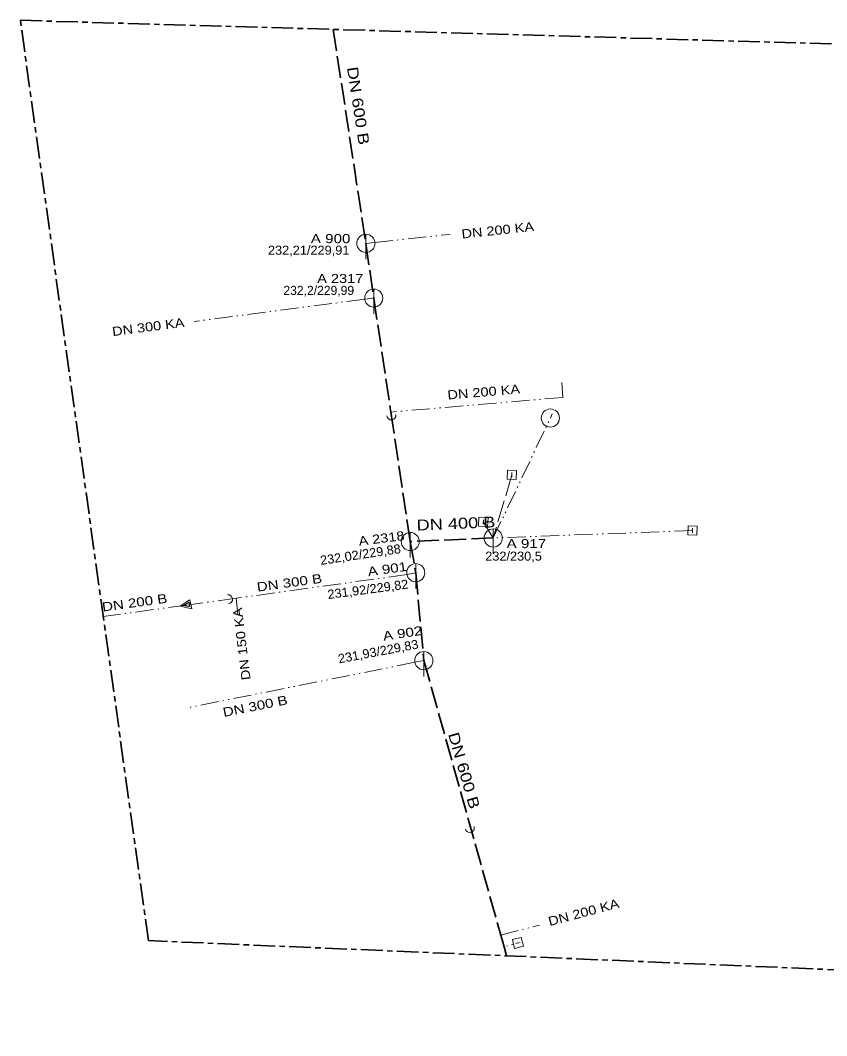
# Model space of a CAD drawing. Extents: x -640241 to -639979, y -1041484 to -1041371.
# Drawn here: x -640241 to -640152.1, y -1041482.8 to -1041370.7 of the extents above; entities that cross this region are included whole.
import ezdxf
from ezdxf.enums import TextEntityAlignment as Align

# ---------------------------------------------------------------- set-up
doc = ezdxf.new("R2010")
doc.units = 0
doc.header["$LTSCALE"] = 0.4
for name, pattern in [('DASH_DOUBLE_DOT', [9.2, 5, -1.2, 0.3, -1.2, 0.3, -1.2]), ('DOTTED', [1.5, 0.3, -1.2]), ('LONG_DASH_SHORT_DASH', [9.9, 6, -1.2, 1.5, -1.2]), ('LONG_DASHED', [7.5, 6, -1.5])]:
    doc.linetypes.add(name, pattern=pattern)
for name, color, linetype, lineweight in [('1', 7, 'LONG_DASH_SHORT_DASH', 35), ('10', 7, 'Continuous', 13), ('14', 7, 'Continuous', 13), ('23', 7, 'LONG_DASHED', 35), ('34', 7, 'DASH_DOUBLE_DOT', 13), ('35', 7, 'LONG_DASHED', 13), ('36', 7, 'DASH_DOUBLE_DOT', 13)]:
    doc.layers.add(name, color=color, linetype=linetype, lineweight=lineweight)
doc.layers.add('29', color=7, linetype='Continuous')
doc.layers.add('39', color=7, linetype='Continuous')

msp = doc.modelspace()

# ---------------------------------------------------------------- linework, layer by layer
at = {"layer": '1'}
msp.add_lwpolyline([(-639990.066, -1041378.027), (-639979.473, -1041482.75), (-640226.879, -1041472.267), (-640241.004, -1041370.744)], close=True, dxfattribs=at)
at = {"layer": '10'}
for p, q in [((-640202.895, -1041394.347), (-640202.895, -1041397.095)), ((-640202.023, -1041400.384), (-640202.023, -1041403.132)), ((-640186.779, -1041420.64), (-640186.801, -1041421.14)), ((-640189.929, -1041425.83), (-640189.951, -1041426.33)), ((-640198, -1041427.24), (-640198, -1041429.988)), ((-640188.85, -1041426.85), (-640188.85, -1041429.598)), ((-640166.859, -1041426.78), (-640166.881, -1041427.28)), ((-640197.39, -1041430.68), (-640197.39, -1041433.428)), ((-640196.5, -1041440.38), (-640196.5, -1041443.128)), ((-640185.879, -1041472.457), (-640186.364, -1041472.579))]:
    msp.add_line(p, q, dxfattribs=at)
for points in [[(-640187.268, -1041420.369), (-640187.311, -1041421.368), (-640186.311, -1041421.41), (-640186.269, -1041420.411)], [(-640190.418, -1041425.559), (-640190.462, -1041426.558), (-640189.463, -1041426.602), (-640189.419, -1041425.603)], [(-640167.348, -1041426.509), (-640167.392, -1041427.508), (-640166.393, -1041427.552), (-640166.349, -1041426.553)], [(-640222.104, -1041435.65), (-640222.293, -1041434.668), (-640223.377, -1041435.385)], [(-640222.293, -1041435.456), (-640222.398, -1041434.915), (-640222.994, -1041435.311)], [(-640185.758, -1041471.912), (-640186.728, -1041472.154), (-640186.485, -1041473.125), (-640185.515, -1041472.882)]]:
    msp.add_lwpolyline(points, close=True, dxfattribs=at)
for centre, radius in [((-640202.8947, -1041395.3473), 1.0002), ((-640202.0227, -1041401.3843), 1.0002), ((-640182.5459, -1041414.6158), 1), ((-640197.9997, -1041428.2403), 1.0002), ((-640188.8497, -1041427.8503), 1.0002), ((-640197.3897, -1041431.6803), 1.0002), ((-640196.4997, -1041441.3803), 1.0002)]:
    msp.add_circle(centre, radius, dxfattribs=at)
at = {"layer": '14'}
for centre, start, end in [((-640200.0859, -1041414.318), 188.5195, 8.5195), ((-640218.0997, -1041434.6169), 277.86851, 97.86851), ((-640191.4295, -1041459.83), 196.04393, 16.04393)]:
    msp.add_arc(centre, 0.5, start, end, dxfattribs=at)
at = {"layer": '23'}
for p, q in [((-640206.498, -1041371.745), (-640202.895, -1041395.347)), ((-640202.895, -1041395.347), (-640202.023, -1041401.384)), ((-640188.85, -1041427.85), (-640198, -1041428.24)), ((-640197.39, -1041431.68), (-640196.5, -1041441.38)), ((-640187.654, -1041472.959), (-640187.371, -1041473.941))]:
    msp.add_line(p, q, dxfattribs=at)
for points in [[(-640202.023, -1041401.384), (-640200.14, -1041413.954), (-640198, -1041428.24), (-640197.39, -1041431.68)], [(-640196.5, -1041441.38), (-640188.022, -1041471.678), (-640187.654, -1041472.959)]]:
    msp.add_lwpolyline(points, dxfattribs=at)
at = {"layer": '34'}
for p, q in [((-640201.901, -1041395.241), (-640193.6, -1041394.357)), ((-640202.895, -1041395.347), (-640201.901, -1041395.241)), ((-640203.015, -1041401.514), (-640221.848, -1041403.974)), ((-640202.023, -1041401.384), (-640203.015, -1041401.514)), ((-640197.39, -1041431.68), (-640198.368, -1041431.889)), ((-640197.483, -1041441.564), (-640222.437, -1041446.555)), ((-640196.5, -1041441.38), (-640197.483, -1041441.564)), ((-640188.022, -1041471.678), (-640183.752, -1041470.542))]:
    msp.add_line(p, q, dxfattribs=at)
for points in [[(-640181.269, -1041410.712), (-640181.167, -1041412.346), (-640200.14, -1041413.954)], [(-640198.368, -1041431.889), (-640217.212, -1041434.493), (-640216.996, -1041436.268)], [(-640217.212, -1041434.493), (-640222.67, -1041435.248), (-640231.853, -1041436.517)]]:
    msp.add_lwpolyline(points, dxfattribs=at)
at = {"layer": '35'}
msp.add_line((-640186.79, -1041420.89), (-640188.85, -1041427.85), dxfattribs=at)
at = {"layer": '36'}
for p, q in [((-640182.546, -1041414.615), (-640182.342, -1041414.141)), ((-640166.87, -1041427.03), (-640188.85, -1041427.85))]:
    msp.add_line(p, q, dxfattribs=at)
at = {"layer": '36', "linetype": 'DOTTED'}
msp.add_line((-640186.122, -1041472.518), (-640187.654, -1041472.959), dxfattribs=at)
at = {"layer": '36'}
msp.add_lwpolyline([(-640189.94, -1041426.08), (-640188.85, -1041427.85), (-640182.546, -1041414.615)], dxfattribs=at)

# ---------------------------------------------------------------- texts
at = {"layer": '29'}
for s, height, rotation, width, p in [('DN 600 B', 1.2, 278.68, 1.25, (-640204.3251, -1041380.2595)), ('DN 400 B', 1.2, 2.442, 1.25, (-640192.9306, -1041426.8488)), ('232,02/229,88', 1, 8.491, 1.05, (-640203.4173, -1041430.1598)), ('231,92/229,82', 1, 7.536, 1.05, (-640202.6041, -1041433.9971)), ('231,93/229,83', 1, 10.648, 1.05, (-640201.4414, -1041440.852)), ('DN 600 B', 1.2, 286.044, 1.25, (-640192.6374, -1041453.6632))]:
    msp.add_text(s, height=height, rotation=rotation, dxfattribs=dict(at, width=width)).set_placement(p, align=Align.CENTER)
for s, width, p in [('A 900', 1.25, (-640208.965, -1041395.323)), ('A 2317', 1.2, (-640208.26, -1041399.721)), ('A 917', 1.25, (-640187.374, -1041428.967))]:
    msp.add_text(s, height=1, dxfattribs=dict(at, width=width)).set_placement(p)
at = {"layer": '29', "width": 1.05}
for s, p in [('232,21/229,91', (-640209.199, -1041396.601)), ('232/230,5', (-640186.605, -1041430.351))]:
    msp.add_text(s, height=1, dxfattribs=at).set_placement(p, align=Align.CENTER)
at = {"layer": '29'}
msp.add_text('232,2/229,99', height=1, dxfattribs=at).set_placement((-640208.09, -1041401.037), align=Align.CENTER)
for s, rotation, width, p in [('A 2318', 7.357, 1.2, (-640203.632, -1041428.712)), ('A 901', 8.008, 1.25, (-640202.619, -1041432.068)), ('A 902', 8.533, 1.25, (-640200.933, -1041439.181))]:
    msp.add_text(s, height=1, rotation=rotation, dxfattribs=dict(at, width=width)).set_placement(p)
at = {"layer": '39'}
for s, rotation, width, p in [('DN 200 KA', 6.079, 1.2, (-640188.2989, -1041394.3947)), ('DN 300 KA', 7.442, 1.2, (-640226.8298, -1041405.062)), ('DN 200 KA', 4.844, 1.2, (-640189.8542, -1041412.2366)), ('DN 300 B', 7.869, 1.25, (-640211.2574, -1041433.2728)), ('DN 200 B', 7.869, 1.25, (-640228.3254, -1041435.4748)), ('DN 150 KA', 96.938, 1.2, (-640216.0837, -1041439.4814)), ('DN 300 B', 11.31, 1.25, (-640215.0071, -1041446.8846)), ('DN 200 KA', 14.898, 1.2, (-640178.7475, -1041469.6301))]:
    msp.add_text(s, height=1, rotation=rotation, dxfattribs=dict(at, width=width)).set_placement(p, align=Align.CENTER)

doc.saveas('drawing.dxf')
